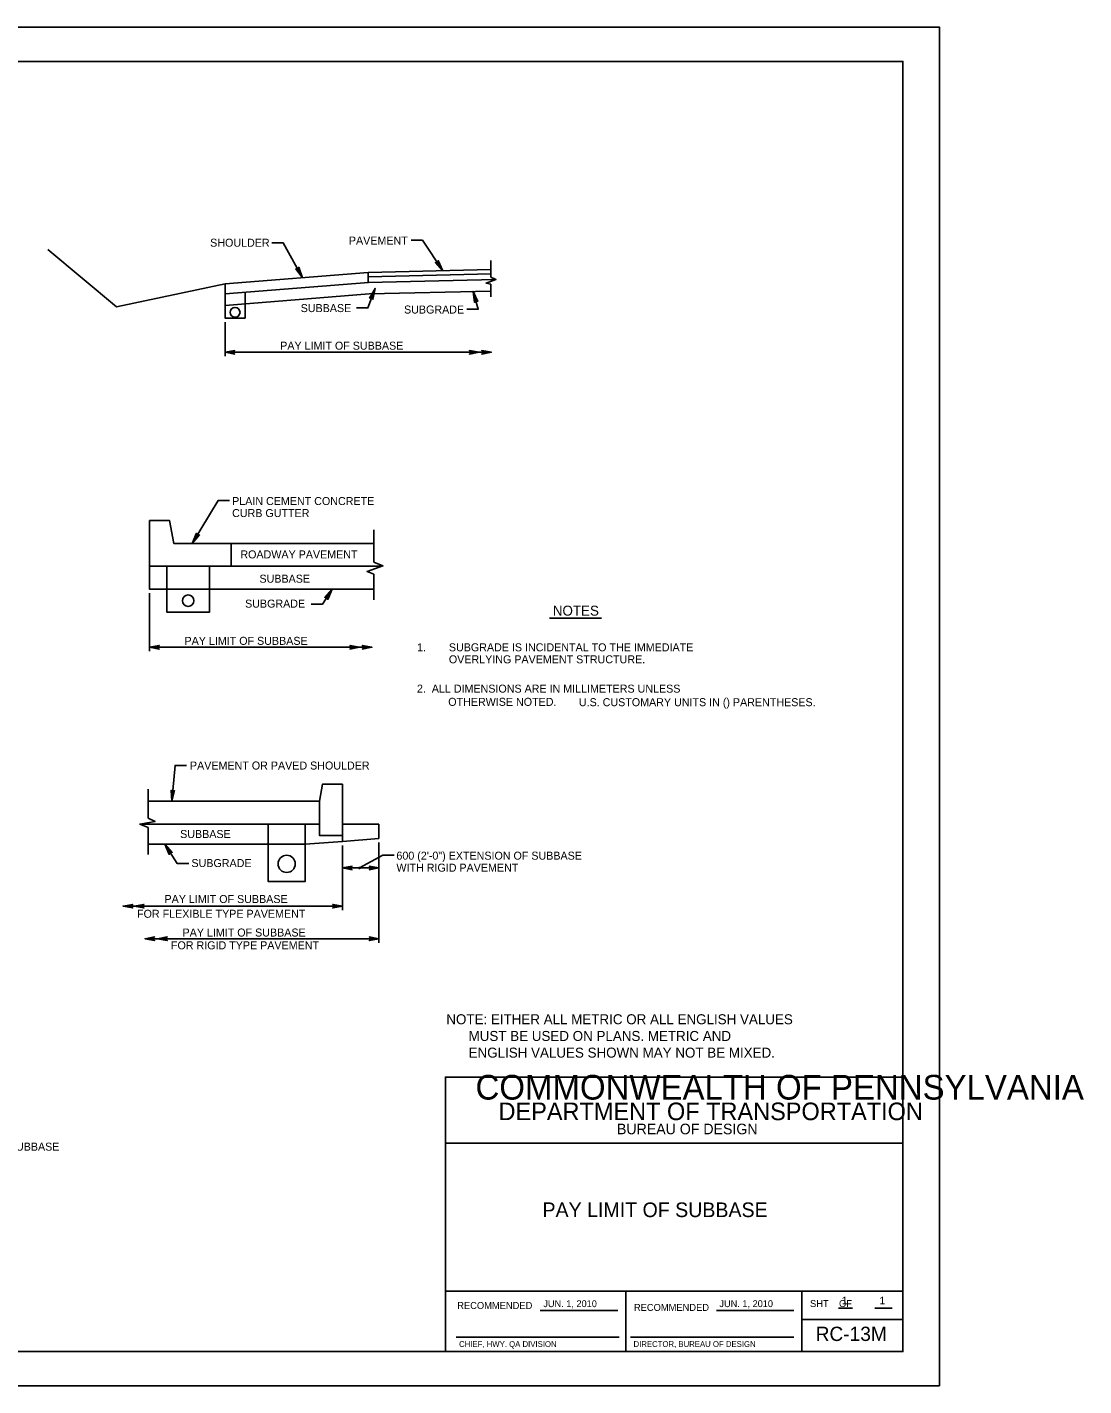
# Model space of a CAD drawing. Extents: x -106 to 798, y -95 to 499.
# Drawn here: x 336 to 798, y -95 to 499 of the extents above; entities that cross this region are included whole.
import ezdxf

# ---------------------------------------------------------------- set-up
doc = ezdxf.new("R2010")
doc.units = 0
for name, color, linetype in [('1', 7, 'Continuous'), ('2', 7, 'Continuous'), ('3', 7, 'Continuous'), ('PLT-BNDY', 7, 'Continuous')]:
    doc.layers.add(name, color=color, linetype=linetype)

msp = doc.modelspace()

# ---------------------------------------------------------------- linework, layer by layer
at = {"layer": '1'}
for p, q in [((560.64, -61.63), (594.52, -61.63)), ((637.63, -61.63), (671.5, -61.63)), ((691.04, -60.65), (697.18, -60.65)), ((706.85, -60.65), (714.49, -60.65)), ((523.93, -73.37), (595.18, -73.37)), ((600.1, -73.37), (671.44, -73.37))]:
    msp.add_line(p, q, dxfattribs=at)
msp.add_lwpolyline([(719.17, -79.62), (719.17, 484.38), (-66.83, 484.38), (-66.83, -79.62), (719.17, -79.62), (719.17, -53.27), (519.17, -53.27), (519.17, 11.41), (719.17, 11.41), (719.17, 40.38), (519.17, 40.38), (519.17, -79.62), (597.97, -79.62), (597.97, -53.27), (597.97, -79.62), (674.97, -79.62), (674.97, -53.27), (674.97, -65.58), (719.17, -65.58)], dxfattribs=at)
at = {"layer": '2'}
for p, q in [((485.33, 392.16), (485.33, 387.78)), ((539.08, 397.33), (539.08, 390.12)), ((539.08, 387.07), (539.08, 381.45)), ((422.83, 370.41), (422.83, 355.47)), ((422.83, 357.22), (490.85, 357.22)), ((490.85, 357.22), (539.3, 357.22)), ((487.91, 279.65), (487.91, 265.41)), ((425.41, 273.66), (487.91, 273.66)), ((425.41, 263.66), (491.4, 263.66)), ((487.91, 260.24), (487.91, 248.97)), ((389.78, 251.91), (389.78, 226.54)), ((397.28, 253.66), (416.03, 253.66)), ((416.03, 253.66), (487.91, 253.66)), ((389.78, 228.29), (448.1, 228.29)), ((448.1, 228.29), (487.01, 228.29)), ((389.13, 166.26), (389.13, 153.49)), ((464.13, 160.92), (389.13, 160.92)), ((464.13, 150.92), (385.36, 150.92)), ((389.13, 149.46), (389.13, 137.66)), ((473.98, 150.95), (490.07, 150.98)), ((490.07, 150.98), (490.07, 144.65)), ((474.13, 143.42), (490.07, 144.65)), ((490.07, 142.9), (490.07, 99.11)), ((441.36, 142.17), (389.13, 142.17)), ((457.88, 142.17), (441.36, 142.17)), ((474.13, 141.67), (474.13, 113.34)), ((474.13, 139.92), (474.13, 130.03)), ((490.07, 141.15), (490.07, 130.03)), ((474.13, 131.78), (490.07, 131.78)), ((443.39, 115.09), (378.25, 115.09)), ((474.13, 115.09), (443.39, 115.09)), ((451.36, 100.86), (387.81, 100.86)), ((490.07, 100.86), (451.36, 100.86))]:
    msp.add_line(p, q, dxfattribs=at)
for points in [[(443.26, 405.06), (448.26, 405.06), (456.67, 389.86)], [(504.12, 406.3), (509.12, 406.3), (518.06, 392.92)], [(539.08, 393.41), (485.33, 392.16), (422.83, 387.16), (375.33, 377.16), (345.33, 402.16)], [(454.97, 394.11), (454.77, 393.81), (456.67, 389.86), (454.97, 394.11), (455.04, 394.41), (456.67, 389.86), (454.37, 393.58), (454.01, 393.56), (456.67, 389.86), (453.7, 393.67), (454.01, 393.56)], [(516.01, 397.01), (515.83, 396.69), (518.06, 392.92), (516.01, 397.01), (516.05, 397.31), (518.06, 392.92), (515.45, 396.43), (515.09, 396.38), (518.06, 392.92), (514.77, 396.46), (515.09, 396.38)], [(485.55, 387.79), (422.83, 382.77)], [(422.83, 387.16), (422.83, 372.16), (431.58, 372.16), (431.58, 383.47)], [(541.08, 389.08), (485.33, 387.78)], [(539.12, 391.53), (485.42, 390.28)], [(539.08, 390.12), (541.22, 389.13), (536.94, 387.52), (539.08, 387.07)], [(539.08, 384.03), (485.81, 382.79), (422.83, 377.75)], [(480.27, 376.6), (485.27, 376.6), (488.37, 385.15)], [(486.28, 381.07), (486.65, 381.12), (488.37, 385.15), (486.28, 381.07), (486.02, 380.92), (488.37, 385.15), (487.08, 380.97), (487.33, 380.71), (488.37, 385.15), (487.45, 380.4), (487.33, 380.71)], [(528.52, 376.04), (533.52, 376.04), (531.22, 383.85)], [(531.96, 379.33), (532.23, 379.59), (531.22, 383.85), (531.96, 379.33), (531.83, 379.05), (531.22, 383.85), (532.66, 379.72), (533.02, 379.66), (531.22, 383.85), (533.3, 379.48), (533.02, 379.66)], [(422.83, 357.22), (427.05, 358.01), (426.72, 357.79), (422.83, 357.22), (426.56, 357.51), (426.51, 357.22), (422.83, 357.22), (426.56, 356.94), (426.72, 356.66), (422.83, 357.22), (427.05, 356.43), (426.72, 356.66), (426.56, 356.94), (426.51, 357.22), (426.56, 357.51), (426.72, 357.79)], [(533.85, 357.22), (529.63, 356.43), (529.95, 356.66), (533.85, 357.22), (530.12, 356.94), (530.17, 357.22), (533.85, 357.22), (530.12, 357.51), (529.95, 357.79), (533.85, 357.22), (529.63, 358.01), (529.95, 357.79), (530.12, 357.51), (530.17, 357.22), (530.12, 356.94), (529.95, 356.66)], [(539.3, 357.22), (535.07, 356.43), (535.4, 356.66), (539.3, 357.22), (535.57, 356.94), (535.61, 357.22), (539.3, 357.22), (535.57, 357.51), (535.4, 357.79), (539.3, 357.22), (535.07, 358.01), (535.4, 357.79), (535.57, 357.51), (535.61, 357.22), (535.57, 356.94), (535.4, 356.66)], [(424.74, 292.39), (419.74, 292.39), (408.47, 273.66)], [(389.78, 263.66), (389.78, 283.66), (398.53, 283.66), (400.41, 273.66), (425.41, 273.66), (425.41, 263.66), (389.78, 263.66)], [(411.3, 277.26), (410.93, 277.29), (408.47, 273.66), (411.3, 277.26), (411.59, 277.36), (408.47, 273.66), (410.54, 277.52), (410.34, 277.82), (408.47, 273.66), (410.28, 278.15), (410.34, 277.82)], [(389.78, 263.66), (389.78, 253.66), (397.28, 253.66), (397.28, 263.66), (416.03, 263.66), (416.03, 243.66), (397.28, 243.66), (397.28, 253.66)], [(487.91, 265.41), (491.86, 263.82), (484.91, 261.4), (487.91, 260.24)], [(460.47, 247.12), (465.47, 247.12), (469.62, 253.66)], [(467.67, 249.52), (467.49, 249.85), (469.62, 253.66), (467.67, 249.52), (467.72, 249.22), (469.62, 253.66), (467.1, 250.09), (466.74, 250.13), (469.62, 253.66), (466.43, 250.04), (466.74, 250.13)], [(389.78, 228.29), (394, 229.08), (393.68, 228.86), (389.78, 228.29), (393.51, 228.57), (393.46, 228.29), (389.78, 228.29), (393.51, 228.01), (393.68, 227.73), (389.78, 228.29), (394, 227.5), (393.68, 227.73), (393.51, 228.01), (393.46, 228.29), (393.51, 228.57), (393.68, 228.86)], [(481.6, 228.29), (477.38, 227.5), (477.71, 227.73), (481.6, 228.29), (477.87, 228.01), (477.92, 228.29), (481.6, 228.29), (477.87, 228.57), (477.71, 228.86), (481.6, 228.29), (477.38, 229.08), (477.71, 228.86), (477.87, 228.57), (477.92, 228.29), (477.87, 228.01), (477.71, 227.73)], [(487.01, 228.29), (482.79, 227.5), (483.12, 227.73), (487.01, 228.29), (483.28, 228.01), (483.33, 228.29), (487.01, 228.29), (483.28, 228.57), (483.12, 228.86), (487.01, 228.29), (482.79, 229.08), (483.12, 228.86), (483.28, 228.57), (483.33, 228.29), (483.28, 228.01), (483.12, 227.73)], [(405.94, 176.64), (400.94, 176.64), (399.55, 160.92)], [(474.13, 168.42), (465.38, 168.42), (464.13, 160.92), (464.13, 145.92), (474.13, 145.92), (474.13, 168.42)], [(400.52, 165.39), (400.17, 165.25), (399.55, 160.92), (400.52, 165.39), (400.73, 165.61), (399.55, 160.92), (399.72, 165.29), (399.41, 165.48), (399.55, 160.92), (399.21, 165.74), (399.41, 165.48)], [(389.13, 153.49), (392.2, 152.04), (385.55, 150.95), (389.13, 149.46)], [(474.13, 145.92), (474.13, 143.42), (457.88, 142.17), (457.88, 150.92)], [(406.9, 133.7), (401.9, 133.7), (396.53, 142.17)], [(398.48, 138.03), (398.67, 138.35), (396.53, 142.17), (398.48, 138.03), (398.44, 137.73), (396.53, 142.17), (399.05, 138.6), (399.41, 138.64), (396.53, 142.17), (399.73, 138.55), (399.41, 138.64)], [(496.76, 137.44), (491.76, 137.44), (481.56, 131.78)], [(474.13, 131.78), (478.35, 132.57), (478.03, 132.35), (474.13, 131.78), (477.86, 132.07), (477.81, 131.78), (474.13, 131.78), (477.86, 131.5), (478.03, 131.22), (474.13, 131.78), (478.35, 130.99), (478.03, 131.22), (477.86, 131.5), (477.81, 131.78), (477.86, 132.07), (478.03, 132.35)], [(490.07, 131.78), (485.85, 130.99), (486.18, 131.22), (490.07, 131.78), (486.35, 131.5), (486.39, 131.78), (490.07, 131.78), (486.35, 132.07), (486.18, 132.35), (490.07, 131.78), (485.85, 132.57), (486.18, 132.35), (486.35, 132.07), (486.39, 131.78), (486.35, 131.5), (486.18, 131.22)], [(378.25, 115.09), (382.47, 115.88), (382.14, 115.65), (378.25, 115.09), (381.97, 115.37), (381.93, 115.09), (378.25, 115.09), (381.97, 114.8), (382.14, 114.52), (378.25, 115.09), (382.47, 114.3), (382.14, 114.52), (381.97, 114.8), (381.93, 115.09), (381.97, 115.37), (382.14, 115.65)], [(383.13, 115.09), (387.35, 115.88), (387.02, 115.65), (383.13, 115.09), (386.86, 115.37), (386.81, 115.09), (383.13, 115.09), (386.86, 114.8), (387.02, 114.52), (383.13, 115.09), (387.35, 114.3), (387.02, 114.52), (386.86, 114.8), (386.81, 115.09), (386.86, 115.37), (387.02, 115.65)], [(474.13, 115.09), (469.91, 114.3), (470.24, 114.52), (474.13, 115.09), (470.4, 114.8), (470.45, 115.09), (474.13, 115.09), (470.4, 115.37), (470.24, 115.65), (474.13, 115.09), (469.91, 115.88), (470.24, 115.65), (470.4, 115.37), (470.45, 115.09), (470.4, 114.8), (470.24, 114.52)], [(387.81, 100.86), (392.03, 101.66), (391.7, 101.43), (387.81, 100.86), (391.54, 101.15), (391.49, 100.86), (387.81, 100.86), (391.54, 100.58), (391.7, 100.3), (387.81, 100.86), (392.03, 100.07), (391.7, 100.3), (391.54, 100.58), (391.49, 100.86), (391.54, 101.15), (391.7, 101.43)], [(393.28, 100.86), (397.5, 101.66), (397.18, 101.43), (393.28, 100.86), (397.01, 101.15), (396.96, 100.86), (393.28, 100.86), (397.01, 100.58), (397.18, 100.3), (393.28, 100.86), (397.5, 100.07), (397.18, 100.3), (397.01, 100.58), (396.96, 100.86), (397.01, 101.15), (397.18, 101.43)], [(490.07, 100.86), (485.85, 100.07), (486.18, 100.3), (490.07, 100.86), (486.35, 100.58), (486.39, 100.86), (490.07, 100.86), (486.35, 101.15), (486.18, 101.43), (490.07, 100.86), (485.85, 101.66), (486.18, 101.43), (486.35, 101.15), (486.39, 100.86), (486.35, 100.58), (486.18, 100.3)]]:
    msp.add_lwpolyline(points, dxfattribs=at)
msp.add_lwpolyline([(457.88, 150.92), (457.88, 125.92), (441.63, 125.92), (441.63, 150.92)], close=True, dxfattribs=at)
for centre, radius in [((427.2, 374.68), 2.16), ((406.66, 248.64), 2.5), ((449.76, 133.56), 3.75), ((481.56, 131.78), 0.274)]:
    msp.add_circle(centre, radius, dxfattribs=at)
at = {"layer": '3'}
msp.add_line((564.7, 240.93), (587.38, 240.93), dxfattribs=at)
at = {"layer": 'PLT-BNDY'}
msp.add_lwpolyline([(-105.83, 499.38), (735.17, 499.38), (735.17, -94.62), (-105.83, -94.62)], close=True, dxfattribs=at)

# ---------------------------------------------------------------- texts
at = {"layer": '1'}
for s, height, p in [('COMMONWEALTH OF PENNSYLVANIA', 10.7834, (532.32, 30.52)), ('DEPARTMENT OF TRANSPORTATION', 7.6843, (542.38, 21.53)), ('BUREAU OF DESIGN', 4.6221, (594.16, 15.36)), ('RECOMMENDED', 3.048, (524.33, -61.03)), ('JUN. 1, 2010', 3, (561.97, -60.21)), ('RECOMMENDED', 3.048, (601.58, -61.87)), ('JUN. 1, 2010', 3, (638.97, -60.21)), ('SHT    OF', 3.048, (678.58, -60.19)), ('1', 3.25, (692.48, -58.96)), ('1', 3.25, (708.97, -58.96)), ('RC-13M', 6.25, (681.04, -75.02)), ('CHIEF, HWY. QA DIVISION', 2.54, (525.12, -77.63)), ('DIRECTOR, BUREAU OF DESIGN', 2.54, (601.4, -77.63))]:
    msp.add_text(s, height=height, dxfattribs=at).set_placement(p)
at = {"layer": '2'}
for s, height, p in [('2.  ALL DIMENSIONS ARE IN MILLIMETERS UNLESS', 3.4998, (506.7, 208.44)), ('OTHERWISE NOTED.', 3.4998, (520.39, 202.66)), ('U.S. CUSTOMARY UNITS IN () PARENTHESES.', 3.4998, (577.52, 202.51)), ('NOTE: EITHER ALL METRIC OR ALL ENGLISH VALUES', 4.375, (519.55, 63.45)), ('      MUST BE USED ON PLANS. METRIC AND', 4.375, (519.55, 56.15)), ('      ENGLISH VALUES SHOWN MAY NOT BE MIXED.', 4.375, (519.55, 48.86))]:
    msp.add_text(s, height=height, dxfattribs=at).set_placement(p)
at = {"layer": '3'}
for s, height, p in [('SHOULDER', 3.5, (416.3, 403.39)), ('PAVEMENT', 3.5, (476.95, 404.33)), ('SUBBASE', 3.5, (455.87, 374.81)), ('SUBGRADE', 3.5, (501.07, 374.17)), ('PAY LIMIT OF SUBBASE', 3.5, (446.92, 358.38)), ('PLAIN CEMENT CONCRETE', 3.5, (425.9, 290.45)), ('CURB GUTTER', 3.5, (425.9, 285.2)), ('ROADWAY PAVEMENT', 3.5, (429.51, 267.12)), ('SUBBASE', 3.5, (437.85, 256.5)), ('SUBGRADE', 3.5, (431.56, 245.6)), ('NOTES', 4.375, (566.12, 242.09)), ('PAY LIMIT OF SUBBASE', 3.5, (405.08, 229.33)), ('1.  ', 3.5, (506.78, 226.5)), ('SUBGRADE IS INCIDENTAL TO THE IMMEDIATE ', 3.5, (520.67, 226.5)), ('OVERLYING PAVEMENT STRUCTURE.', 3.5, (520.67, 221.25)), ('PAVEMENT OR PAVED SHOULDER', 3.5, (407.46, 174.82)), ('SUBBASE', 3.5, (403.17, 144.87)), ('600 (2\'-0") EXTENSION OF SUBBASE', 3.5, (497.74, 135.41)), ('SUBGRADE', 3.5, (408.12, 132.18)), ('WITH RIGID PAVEMENT', 3.5, (497.74, 130.16)), ('PAY LIMIT OF SUBBASE', 3.5, (396.33, 116.46)), ('FOR FLEXIBLE TYPE PAVEMENT', 3.5, (384.33, 110.01)), ('PAY LIMIT OF SUBBASE', 3.5, (404.22, 101.8)), ('FOR RIGID TYPE PAVEMENT', 3.5, (399.15, 96.22)), ('*CONSIDER THE PAYMENT FOR THIS AREA OF SUBBASE', 3.5, (220.88, 8.19)), ('PAY LIMIT OF SUBBASE', 6.4, (561.6, -20.86))]:
    msp.add_text(s, height=height, dxfattribs=at).set_placement(p)

doc.saveas('drawing.dxf')
